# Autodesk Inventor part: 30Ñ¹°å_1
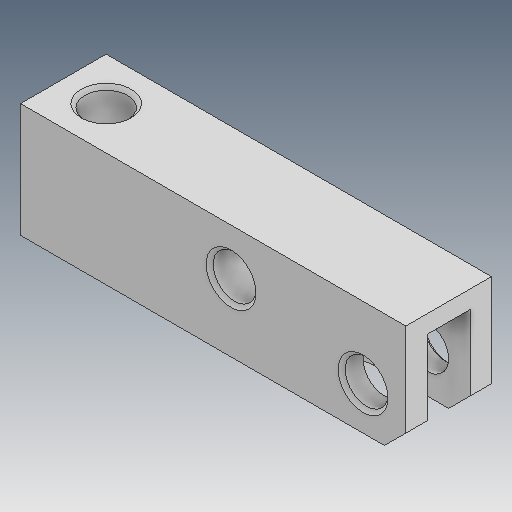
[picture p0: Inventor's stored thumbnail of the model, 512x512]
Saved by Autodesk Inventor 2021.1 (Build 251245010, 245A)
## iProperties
Created: 2019-04
Part Number: 30Ñ¹°å_1
Material: Ogólny
Document SubType Name: Modeling
Designer: user
Density: 1 g/cm^3
Appearance: Domyślna
Author: user
Revision Number: ÈÎºÎ
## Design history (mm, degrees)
feature "ÊäÈë1"
node "Bryła1"
